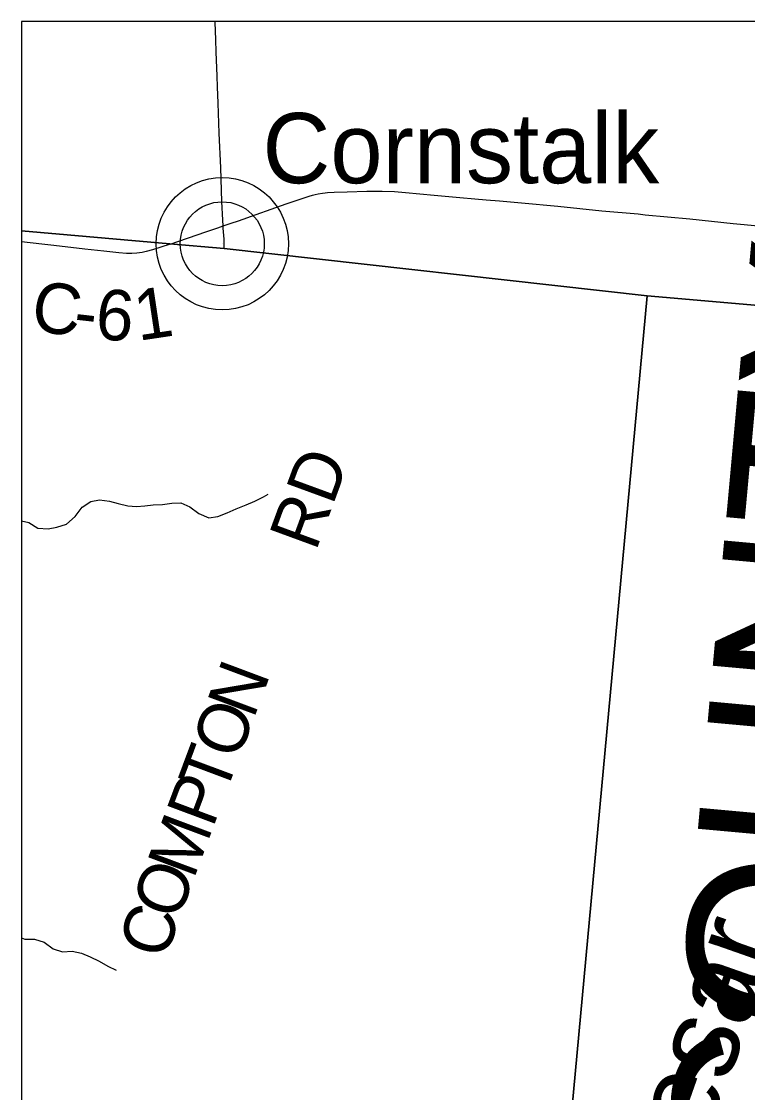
# Model space of a CAD drawing. Extents: x -1.4 to 35.4, y 0 to 22.
# Drawn here: x 2.2 to 3.016, y 18.65 to 19.855 of the extents above; entities that cross this region are included whole.
import ezdxf

# ---------------------------------------------------------------- set-up
doc = ezdxf.new("R2010")
doc.units = 0
for name, color, linetype in [('Default', 7, 'Continuous'), ('GM_X_County_Road', 7, 'Continuous'), ('GM_X_County_Road_Text', 7, 'Continuous'), ('GM_X_County_Text', 7, 'Continuous'), ('GM_X_Major_River_Text', 7, 'Continuous'), ('GM_X_Minor_River', 7, 'Continuous'), ('GM_X_Township_Road', 7, 'Continuous'), ('GM_X_Unincorporated', 7, 'Continuous'), ('GM_X_Unincorporated_Location', 7, 'Continuous'), ('GM_X_Unincorporated_Text', 7, 'Continuous'), ('SH_Border', 7, 'Continuous'), ('SH_Cut_Line', 7, 'Continuous')]:
    doc.layers.add(name, color=color, linetype=linetype)

msp = doc.modelspace()

# ---------------------------------------------------------------- linework, layer by layer
at = {"layer": 'Default'}
for points in [[(5.9686, 19.8546), (2.2, 19.8546), (2.2, 19.619), (2.3668, 19.6046), (2.4279, 19.5993), (2.9037, 19.5459), (3.4296, 19.5001), (3.4459, 19.4989), (4.2528, 19.417), (5.7921, 19.2341)], [(2.7894, 18.3098), (2.9037, 19.5459), (2.4279, 19.5993), (2.3668, 19.6046), (2.2, 19.619), (2.2, 17.406)], [(7.693, 16.8959), (7.7561, 17.6322), (7.8789, 18.9217), (7.8947, 19.0723), (6.8306, 19.1588), (5.7921, 19.2341), (4.2528, 19.417), (3.4459, 19.4989), (3.4296, 19.5001), (2.9037, 19.5459), (2.7894, 18.3098), (2.7365, 17.7956), (2.7172, 17.4718), (2.7109, 17.4025), (2.7066, 17.3545), (2.7033, 17.3163), (2.7006, 17.2849), (2.6906, 17.1666), (2.6843, 17.0961), (2.6688, 16.9164)]]:
    msp.add_lwpolyline(points, dxfattribs=at)
at = {"layer": 'GM_X_County_Road'}
for points in [[(2.4267, 19.6246), (2.4357, 19.6276), (2.4439, 19.6304), (2.4638, 19.6374), (2.4978, 19.6494), (2.519, 19.6566), (2.5235, 19.658), (2.5274, 19.6591), (2.5304, 19.6599), (2.5335, 19.6605), (2.5384, 19.6614), (2.5414, 19.6617), (2.544, 19.662), (2.5515, 19.6624), (2.5664, 19.6629), (2.5882, 19.6635), (2.6056, 19.6635), (2.6193, 19.6631), (2.6317, 19.6622), (2.6639, 19.6592), (2.693, 19.6564), (2.7097, 19.655), (2.7227, 19.6539), (2.7375, 19.6528), (2.7622, 19.6506), (2.803, 19.6468), (2.8525, 19.6416), (2.8933, 19.638), (2.9013, 19.6372)], [(2.9013, 19.6372), (2.9514, 19.6324), (3.0003, 19.6274), (3.0126, 19.6262), (3.0398, 19.6236)], [(2.3671, 19.6041), (2.4074, 19.6181), (2.4208, 19.6226), (2.4267, 19.6246)], [(2.3671, 19.6041), (2.3474, 19.5977), (2.3403, 19.5957), (2.3357, 19.5946), (2.3297, 19.5938), (2.3242, 19.5935), (2.318, 19.5936), (2.3094, 19.5942), (2.2927, 19.5961), (2.2713, 19.5986), (2.2366, 19.6026), (2.223, 19.6042), (2.2, 19.6068)]]:
    msp.add_lwpolyline(points, dxfattribs=at)
at = {"layer": 'GM_X_Minor_River'}
for points in [[(2.2, 19.2927), (2.2084, 19.2909), (2.2185, 19.2846), (2.2302, 19.2839), (2.2398, 19.2859), (2.2505, 19.2891), (2.2606, 19.2979), (2.2681, 19.3084), (2.2781, 19.3146), (2.2877, 19.3166), (2.299, 19.3148), (2.3088, 19.3122), (2.3198, 19.3097), (2.3293, 19.309), (2.3388, 19.3099), (2.3483, 19.3108), (2.3586, 19.3113), (2.3692, 19.3129), (2.3791, 19.313), (2.3892, 19.3086), (2.3993, 19.3011), (2.4106, 19.2962), (2.4209, 19.2978), (2.4312, 19.3018), (2.4416, 19.3064), (2.4527, 19.3107), (2.4623, 19.315), (2.4723, 19.32), (2.4773, 19.323)], [(2.2, 18.8237), (2.204, 18.8222), (2.2147, 18.8223), (2.2256, 18.819), (2.2356, 18.8115), (2.2462, 18.8082), (2.2572, 18.809), (2.2674, 18.8065), (2.2772, 18.8024), (2.2873, 18.7976), (2.297, 18.792), (2.3064, 18.7876)]]:
    msp.add_lwpolyline(points, dxfattribs=at)
at = {"layer": 'GM_X_Township_Road'}
for points in [[(2.4267, 19.6246), (2.4263, 19.6309), (2.4254, 19.652), (2.4241, 19.6898), (2.4224, 19.7289), (2.4212, 19.7625), (2.4205, 19.7811), (2.42, 19.7929), (2.419, 19.8202), (2.4184, 19.8338), (2.4177, 19.8537), (2.4177, 19.8546)], [(2.4281, 19.5988), (2.4278, 19.6098), (2.4269, 19.6222), (2.4267, 19.6246)]]:
    msp.add_lwpolyline(points, dxfattribs=at)
at = {"layer": 'GM_X_Unincorporated'}
for radius in [0.0744, 0.0472]:
    msp.add_circle((2.4258, 19.6045), radius, dxfattribs=at)
at = {"layer": 'GM_X_Unincorporated_Location'}
msp.add_line((2.4258, 19.6045), (2.4258, 19.6045), dxfattribs=at)
at = {"layer": 'SH_Border'}
msp.add_lwpolyline([(9, 19.8546), (2.2, 19.8546), (2.2, 13.0546), (9, 13.0546)], close=True, dxfattribs=at)
at = {"layer": 'SH_Cut_Line'}
for points in [[(9, 18.9633), (9, 19.8546), (2.2, 19.8546), (2.2, 19.619), (2.3668, 19.6046), (2.4279, 19.5993), (2.9037, 19.5459), (3.4296, 19.5001), (3.4459, 19.4989), (4.2528, 19.417), (5.7921, 19.2341), (6.8306, 19.1588), (7.8947, 19.0723), (8.143, 19.049)], [(2.2, 19.619), (2.2, 13.0546), (2.3288, 13.0546), (2.3914, 13.7798), (2.4607, 14.5392), (2.4708, 14.7557), (2.6641, 16.8609), (2.6688, 16.9164), (2.6843, 17.0961), (2.6906, 17.1666), (2.7006, 17.2849), (2.7033, 17.3163), (2.7066, 17.3545), (2.7109, 17.4025), (2.7172, 17.4718), (2.7365, 17.7956), (2.7894, 18.3098), (2.9037, 19.5459), (2.4279, 19.5993), (2.3668, 19.6046)]]:
    msp.add_lwpolyline(points, close=True, dxfattribs=at)
msp.add_lwpolyline([(9, 13.0546), (9, 18.9633), (8.143, 19.049), (7.8947, 19.0723), (6.8306, 19.1588), (5.7921, 19.2341), (4.2528, 19.417), (3.4459, 19.4989), (3.4296, 19.5001), (2.9037, 19.5459), (2.7894, 18.3098), (2.7365, 17.7956), (2.7172, 17.4718), (2.7109, 17.4025), (2.7066, 17.3545), (2.7033, 17.3163), (2.7006, 17.2849), (2.6906, 17.1666), (2.6843, 17.0961), (2.6688, 16.9164)], dxfattribs=at)

# ---------------------------------------------------------------- texts
at = {"layer": 'GM_X_County_Road_Text'}
for s, height, rotation, p in [('C', 0.0568, 351.9019, (2.2091, 19.5074)), ('1', 0.0568, 8.5238, (2.3313, 19.4952)), ('6', 0.0568, 354.9505, (2.2818, 19.4979)), ('-', 0.0568, 353.5003, (2.2571, 19.5007)), ('RD', 0.05682, 69.8498, (2.5309, 19.2575)), ('N', 0.0568, 69.4966, (2.461, 19.069)), ('O', 0.0568, 69.4955, (2.4435, 19.0222)), ('T', 0.0568, 69.4957, (2.4286, 18.9824)), ('P', 0.0568, 69.4946, (2.4152, 18.9465)), ('M', 0.0568, 69.4918, (2.3936, 18.8887)), ('O', 0.0568, 69.438, (2.376, 18.8418)), ('C', 0.0568, 73.5265, (2.3631, 18.7981))]:
    msp.add_text(s, height=height, rotation=rotation, dxfattribs=at).set_placement(p)
at = {"layer": 'GM_X_County_Text'}
msp.add_text('CLINTON COUNTY', height=0.189394, rotation=84.8034, dxfattribs=at).set_placement((3.006, 17.3544))
at = {"layer": 'GM_X_Major_River_Text'}
msp.add_text('Caesar', height=0.09474, rotation=70.6001, dxfattribs=at).set_placement((2.9165, 18.4406))
at = {"layer": 'GM_X_Unincorporated_Text'}
msp.add_text('Cornstalk', height=0.07898, rotation=0, dxfattribs=at).set_placement((2.471, 19.6726))

doc.saveas('drawing.dxf')
